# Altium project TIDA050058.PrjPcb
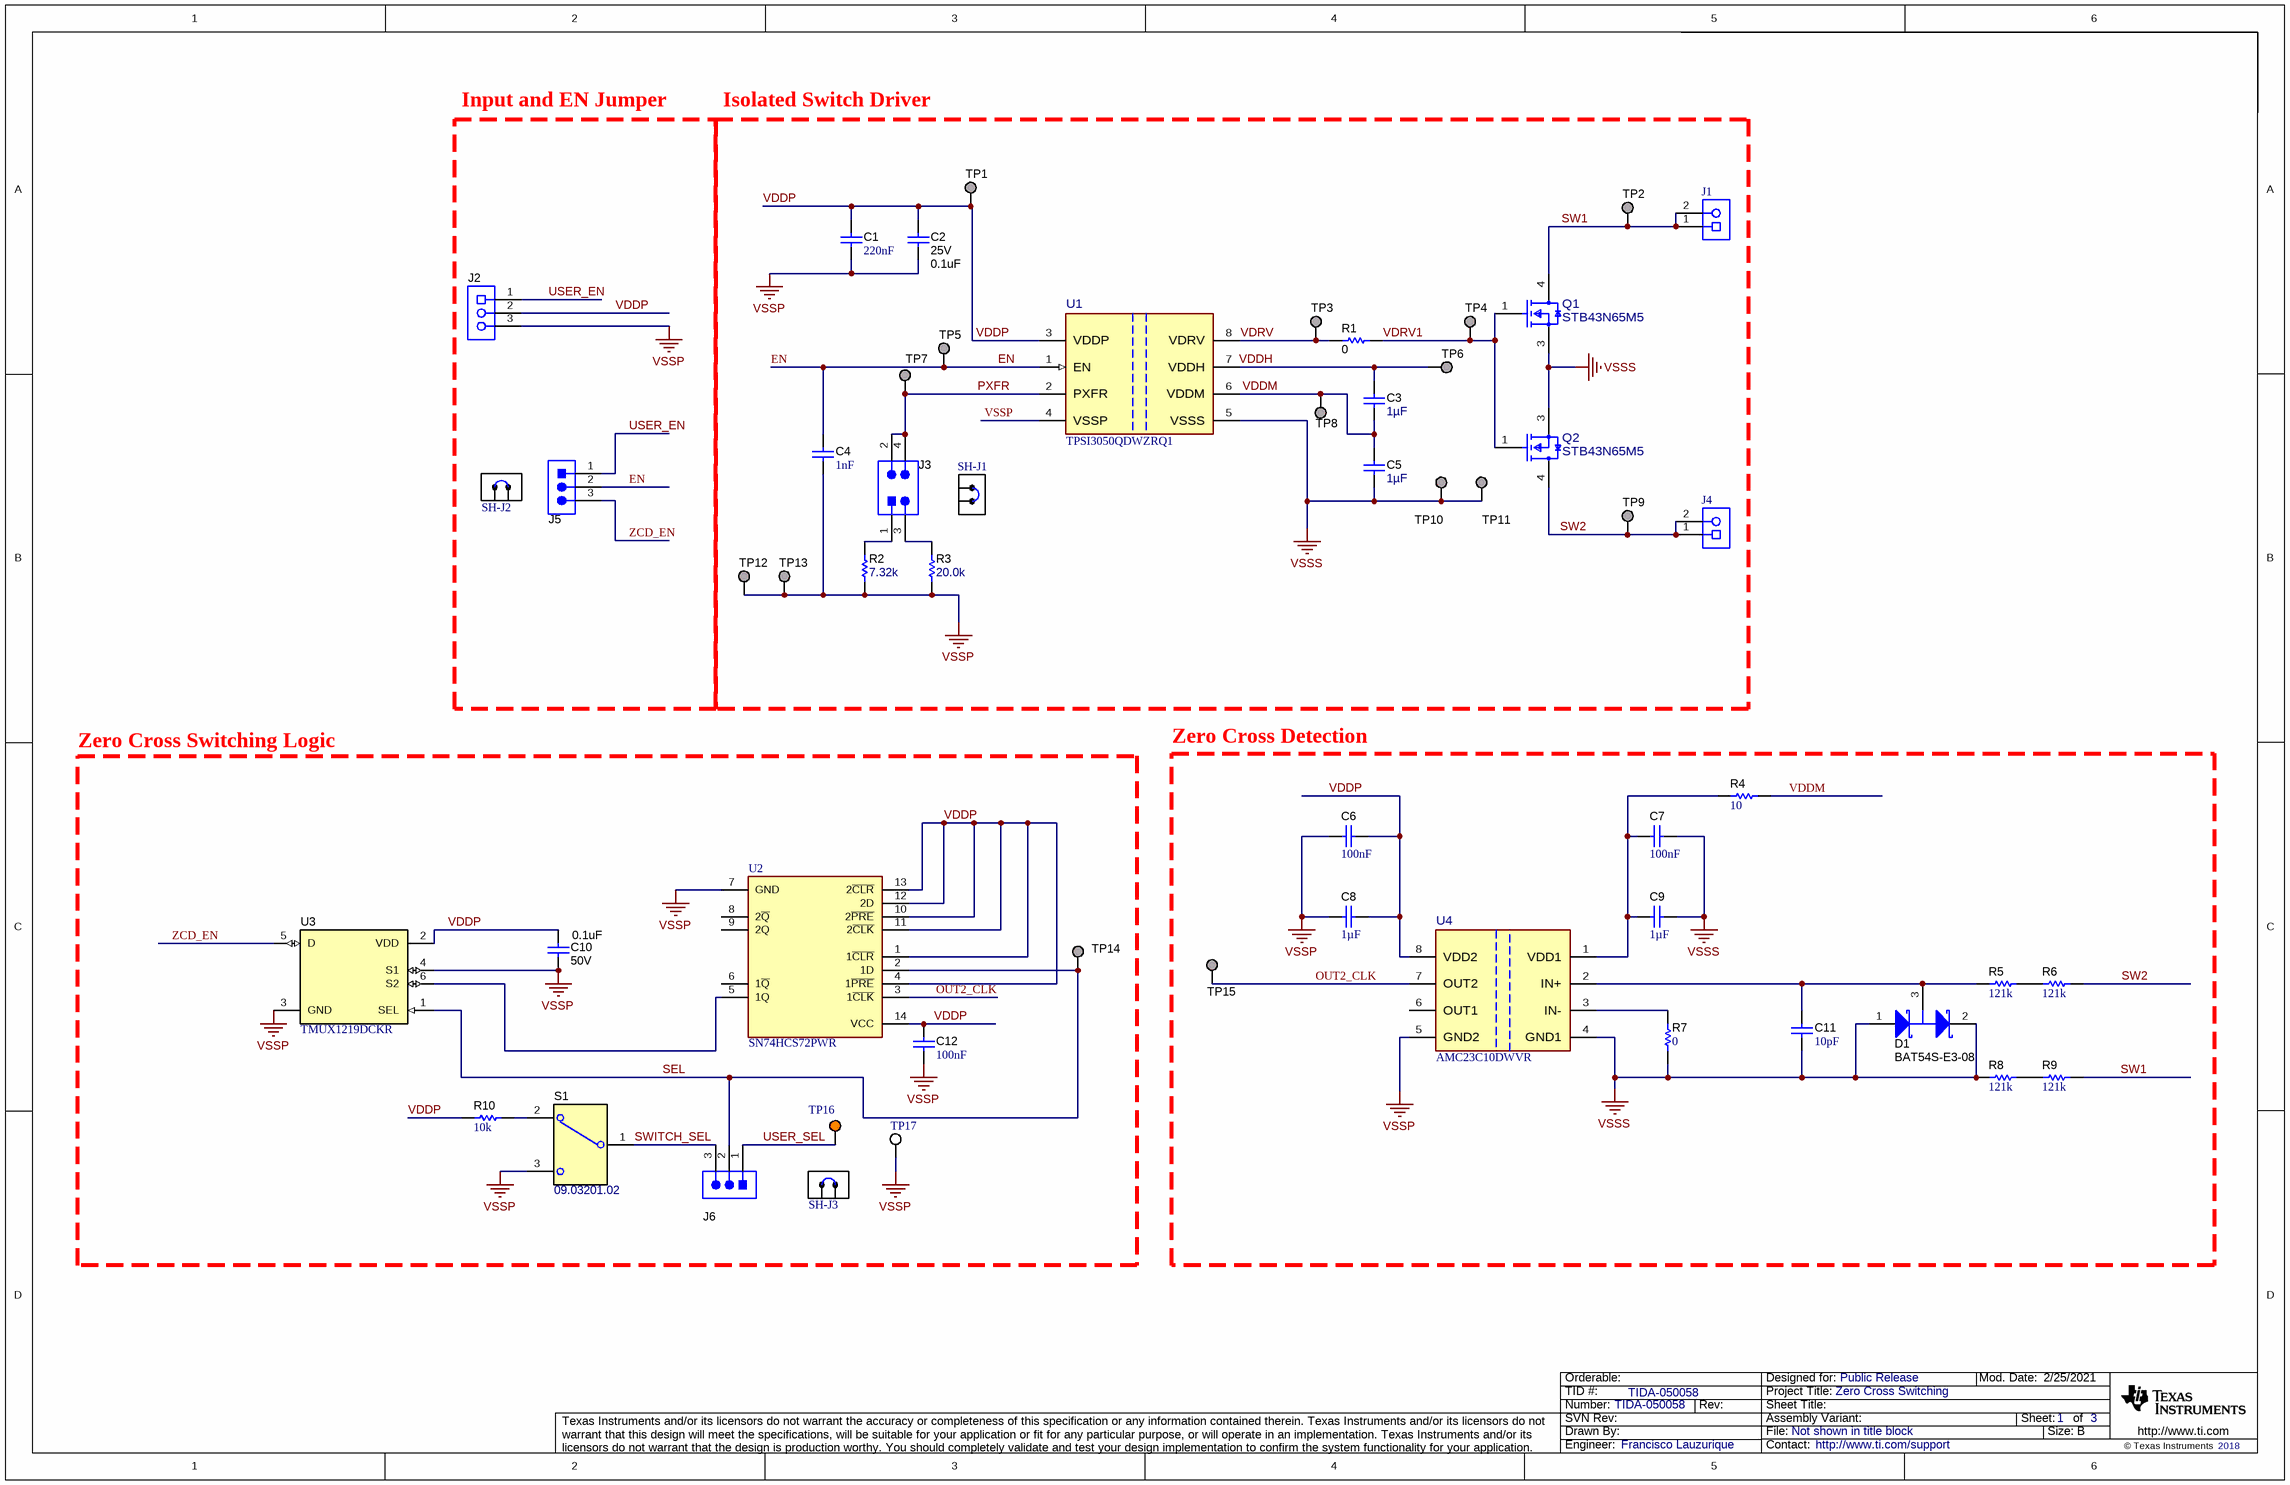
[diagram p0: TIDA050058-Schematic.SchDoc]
CopyrightYear: 2018; PCB_Layout: Francisco Lauzurique; PCB_Rev: E1; PRJ_Customer: Public Release; PRJ_Engineer: Francisco Lauzurique; PRJ_Number: TIDA-050058; PRJ_Title: Zero Cross Switching; TechSupport: http://www.ti.com/support; TID: TIDA-050058
2 sheets, 72 parts. Net scope: global (net labels, ports and power ports of the same name join across sheets).
Board file: TIDA050058-PCB.PcbDoc
Sheets:
  TIDA050058-Schematic.SchDoc
  TIDA050058-Hardware.SchDoc

## Sheet TIDA050058-Schematic.SchDoc
size 431 x 279 mm; Date: Not shown in title block; ApprovedBy: Not shown in title block; CheckedBy: Not shown in title block; Author: Not shown in title block; CompanyName: Not shown in title block; Engineer: Not shown in title block; Organization: Not shown in title block; Address1: Not shown in title block; Address2: Not shown in title block; Address3: Not shown in title block; Address4: Not shown in title block; DocumentNumber: 1; Revision: Use project parameter SCH_Rev; SheetNumber: 1; SheetTotal: 3; PageSetup: Record=PageOptions¦CenterHorizontal=True¦CenterVertical=True¦PrintScale=1.00¦XCorrection=1.00¦YCorrection=1.00¦PrintKind=0¦BorderSize=5000000¦LeftOffset=0¦BottomOffset=0¦Orientation=2¦PaperLength=1000¦PaperWidth=1000¦Scale=100¦PaperSource=15¦PrintQuality=600¦MediaType=1¦DitherType=10¦PaperKind=Letter¦PrintScaleMode=1

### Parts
C1  Cap_F: 220nF  [0603]  (hidden comment: GRM188R71E224KA88D)
C2  VDC_V: 25V  ValueDisplayed: 0.1uF  [0402]  (hidden comment: GRM155R71E104KE14D)
C3  Cap_F: 1µF  [0603]  (hidden comment: UMK107AB7105KA-T)
C4  Cap_F: 1nF  [0603]  (hidden comment: C0603C102J5RACAUTO)
C5  Cap_F: 1µF  [0603]  (hidden comment: UMK107AB7105KA-T)
C6  Cap_F: 100nF  [0603]  (hidden comment: GCM188R71E104KA57D)
C7  Cap_F: 100nF  [0603]  (hidden comment: GCM188R71E104KA57D)
C8  Cap_F: 1µF  [0603]  (hidden comment: GCM188R71E105KA64D)
C9  Cap_F: 1µF  [0603]  (hidden comment: GCM188R71E105KA64D)
C10  VDC_V: 50V  ValueDisplayed: 0.1uF  [0402]  (hidden comment: CGA2B3X7R1H103K050BB)
C11  Cap_F: 10pF  [0603]  (hidden comment: 0603ZC100KAT2A)
C12  Cap_F: 100nF  [0603]  (hidden comment: GCM188R71E104KA57D)
D1  BAT54S-E3-08  [SOT-23]
J1  0393570002  [MOLEX_39357-0002]  (value not drawn)
J2  0393570003  [MOLEX_39357-0003]  (value not drawn)
J3  PBC02DAAN  [Sullins_PxC02DAAN]  (value not drawn)
J4  0393570002  [MOLEX_39357-0002]  (value not drawn)
J5  PEC03SAAN  [CONN_PEC03SAAN]  (value not drawn)
J6  PEC03SAAN  [CONN_PEC03SAAN]  (value not drawn)
Q1  STB43N65M5  [FP-STB43N65M5_D2PAK-MFG]
Q2  STB43N65M5  [FP-STB43N65M5_D2PAK-MFG]
R1  ValueDisplayed: 0  [0603]  (hidden comment: ERJ-3GEY0R00V)
R2  ValueDisplayed: 7.32k  [0603]  (hidden comment: CRCW06037K32FKEA)
R3  ValueDisplayed: 20.0k  [0603]  (hidden comment: CRCW060320K0FKEA)
R4  ValueDisplayed: 10  [0603]  (hidden comment: CRCW060310R0JNEA)
R5  ValueDisplayed: 121k  [2010]  (hidden comment: CRCW2010121KFKEF)
R6  ValueDisplayed: 121k  [2010]  (hidden comment: CRCW2010121KFKEF)
R7  ValueDisplayed: 0  [0603]  (hidden comment: RC0603JR-070RL)
R8  ValueDisplayed: 121k  [2010]  (hidden comment: CRCW2010121KFKEF)
R9  ValueDisplayed: 121k  [2010]  (hidden comment: CRCW2010121KFKEF)
R10  ValueDisplayed: 10k  [0603]  (hidden comment: CRCW060310K0JNEA)
S1  09.03201.02  [SW_09_03201_02]
SH-J1  SNT-100-BK-G  [SNT-100-BK-G]  (value not drawn)
SH-J2  SNT-100-BK-G  [SNT-100-BK-G]  (value not drawn)
SH-J3  SNT-100-BK-G  [SNT-100-BK-G]  (value not drawn)
TP1  5019  [Keystone_5019]  (value not drawn)
TP2  5019  [Keystone_5019]  (value not drawn)
TP3  5019  [Keystone_5019]  (value not drawn)
TP4  5019  [Keystone_5019]  (value not drawn)
TP5  5019  [Keystone_5019]  (value not drawn)
TP6  5019  [Keystone_5019]  (value not drawn)
TP7  5019  [Keystone_5019]  (value not drawn)
TP8  5019  [Keystone_5019]  (value not drawn)
TP9  5019  [Keystone_5019]  (value not drawn)
TP10  5019  [Keystone_5019]  (value not drawn)
TP11  5019  [Keystone_5019]  (value not drawn)
TP12  5019  [Keystone_5019]  (value not drawn)
TP13  5019  [Keystone_5019]  (value not drawn)
TP14  5019  [Keystone_5019]  (value not drawn)
TP15  5019  [Keystone_5019]  (value not drawn)
TP16  5010  [Keystone5013]  (value not drawn)
TP17  5012  [Keystone5012]  (value not drawn)
U1  TPSI3050QDWZRQ1  [DWZ0008A-MFG]
U2  SN74HCS72PWR  [FP-PW0014A-IPC_C]
U3  TMUX1219DCKR  [DCK0006A_N]  (no BOM)
U4  AMC23C10DWVR  [DWV0008A-MFG]

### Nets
VSSP: C1.2 C2.2 C4.2 C6.2 C8.2 C10.2 C12.2 J2.3 R2.1 R3.1 S1.3 TP12.1 TP13.1 TP17.1 U1.4(VSSP) U2.7(GND) U3.3(GND) U3.4(S1) U4.5(GND2)
VSSS: C5.2 C7.1 C9.1 C11.2 D1.1(A) D1.2(K) Q1.3(S) Q2.3(S) R7.1 R8.1 TP10.1 TP11.1 U1.5(VSSS) U4.4(GND1)
EN: C4.1 J5.2 TP5.1 U1.1(EN)
OUT2_CLK: TP15.1 U2.3(1~{CLK}) U4.7(OUT2)
PXFR: J3.2 J3.4 TP7.1 U1.2(PXFR)
SEL: J6.2 TP14.1 U2.2(1D) U3.1(SEL)
SW1: J1.1 J1.2 Q1.4(D) R9.2 TP2.1
SW2: J4.1 J4.2 Q2.4(D) R6.2 TP9.1
SWITCH_SEL: J6.3 S1.1
USER_EN: J2.1 J5.1
USER_SEL: J6.1 TP16.1
VDDM: C3.2 C5.1 R4.2 TP8.1 U1.6(VDDM)
VDDP: C1.1 C2.1 C6.1 C8.1 C10.1 C12.1 J2.2 R10.1 TP1.1 U1.3(VDDP) U2.1(1~{CLR}) U2.4(1~{PRE}) U2.10(2~{PRE}) U2.11(2~{CLK}) U2.12(2D) U2.13(2~{CLR}) U2.14(VCC) U3.2(VDD) U4.8(VDD2)
VDRV: R1.1 TP3.1 U1.8(VDRV)
VDRV1: Q1.1(G) Q2.1(G) R1.2 TP4.1
ZCD_EN: J5.3 U3.5(D)
NetC3_1: C3.1 TP6.1 U1.7(VDDH)
NetC7_2: C7.2 C9.2 R4.1 U4.1(VDD1)
NetC11_1: C11.1 D1.3(C) R5.1 U4.2(IN+)
NetJ3_1: J3.1 R2.2
NetJ3_3: J3.3 R3.2
NetR5_2: R5.2 R6.1
NetR7_2: R7.2 U4.3(IN-)
NetR8_2: R8.2 R9.1
NetR10_2: R10.2 S1.2
NetU2_5: U2.5(1Q) U3.6(S2)

Not connected (* = marked no-connect by the designer): U2 6(1~{Q}) 8(2~{Q}) 9(2Q); U4 6(OUT1)

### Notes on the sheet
- Input and EN Jumper
- Isolated Switch Driver
- Zero Cross Switching Logic
- Zero Cross Detection
- Labels drawn without touching a wire or pin: VDDH

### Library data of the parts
C1 = CMP-0007415-4: CAP, CERM, 0.22 uF, 25 V, +/- 10%, X7R, 0603; Manufacturer: MuRata; TaMin_C: -55°C; Polarized: N; SizeAreaWB_mm2: 4.68; Value1: Unknown; U/M: EA; Value: 0.22uF; TaMax_C: 125°C; SizeZ_mm: 1; SizeX_mm: 1.6; SizeY_mm: 0.8; Value2: 25V; SizeArea_mm2: 1.28; AEC Category: Q200
C2 = CMP-0006659-2: CAP, CERM, 0.1 uF, 25 V, +/- 10%, X7R, 0402; Manufacturer: MuRata; TaMin_C: -55°C; Polarized: N; SizeAreaWB_mm2: 3; Value1: Unknown; U/M: EA; Value: 0.1uF; TaMax_C: 125°C; SizeZ_mm: 0.6; SizeX_mm: 1; SizeY_mm: 0.5; CompType: Capacitor; Cap_F: 100nF; AEC Category: Q200
C3 C5 = CMP-0007508-5: CAP, CERM, 1 uF, 50 V, +/- 10%, X7R, 0603; Manufacturer: Taiyo Yuden; TaMin_C: -55°C; Polarized: N; SizeAreaWB_mm2: 4.68; Value1: Unknown; U/M: EA; Value: 1uF; TaMax_C: 125°C; SizeZ_mm: 1; SizeX_mm: 1.6; SizeY_mm: 0.8; Value2: 50V; SizeArea_mm2: 1.28; AEC Category: Q200
C4 = CMP-0006844-4: CAP, CERM, 1000 pF, 50 V, +/- 5%, X7R, AEC-Q200 Grade 1, 0603; Manufacturer: Kemet; TaMin_C: -55°C; Polarized: N; SizeAreaWB_mm2: 4.68; Value1: Unknown; U/M: EA; Value: 1000pF; TaMax_C: 125°C; SizeZ_mm: 1; SizeX_mm: 1.6; SizeY_mm: 0.8; Value2: 50V; SizeArea_mm2: 1.28; AEC Qualified: Y; AEC Category: Q200
C6 C7 C12 = CMP-0084679-1: CAP, CERM, 0.1 µF, 25 V,+/- 10%, X7R, AEC-Q200 Grade 1, 0603; Manufacturer: MuRata; VDC_V: 25V; TaMin_C: -55°C; SizeY_mm: 0.8; Polarized: N; SizeArea_mm2: 1.28; SizeZ_mm: 1; SizeX_mm: 1.6; AEC Qualified: Y; AEC Category: Q200; Value: 0.1uF; ValueDisplayed: 0.1µF; TaMax_C: 125°C; U/M: EA; SizeAreaWB_mm2: 4.68
C8 C9 = CMP-0007139-4: CAP, CERM, 1 uF, 25 V, +/- 10%, X7R, AEC-Q200 Grade 1, 0603; Manufacturer: MuRata; TaMin_C: -55°C; Polarized: N; SizeAreaWB_mm2: 4.68; Value1: Unknown; U/M: EA; Value: 1uF; TaMax_C: 125°C; SizeZ_mm: 1; SizeX_mm: 1.6; SizeY_mm: 0.8; Value2: 25V; SizeArea_mm2: 1.28; AEC Qualified: Y; AEC Category: Q200
C10 = CMP-0006324-2: CAP, CERM, 0.01 uF, 50 V, +/- 10%, X7R, AEC-Q200 Grade 1, 0402; Manufacturer: TDK; TaMin_C: -55°C; ESR_ohm: 3.33065d; Polarized: N; SizeAreaWB_mm2: 3; Value1: 0.333065 ohm; U/M: EA; Value: 0.01uF; TaMax_C: 125°C; SizeZ_mm: 0.6; SizeX_mm: 1; SizeY_mm: 0.5; CompType: Capacitor; AEC Qualified: Y; Cap_F: 10nF; IRMS_A: 3.23373dA; AEC Category: Q200
C11 = CMP-0006811-4: CAP, CERM, 10 pF, 10 V, +/- 10%, X7R, 0603; Manufacturer: AVX; TaMin_C: -55°C; Polarized: N; SizeAreaWB_mm2: 4.68; Value1: Unknown; U/M: EA; Value: 10pF; TaMax_C: 125°C; SizeZ_mm: 1; SizeX_mm: 1.6; SizeY_mm: 0.8; Value2: 10V; SizeArea_mm2: 1.28; AEC Category: Q200
D1 = CMP-0028631-2: Diode, Schottky, 30 V, 0.2 A, SOT-23; Manufacturer: Vishay-Semiconductor; AEC Category: Q101; SizeX_mm: 2.5; Green_REACh: Incomplete; Value: 30V; SizeY_mm: 3; Value1: 0.2A; TJmax_C: 125°C; Value2: 0.7V; SizeArea_mm2: 7.5; SizeZ_mm: 1.1; Io_A: 200mA; Vf_V: 700mV; Green_Lifecycle: Not Set; SizeAreaWB_mm2: 14
J1 J4 = CMP-0055341-2: Terminal Block, 3.5 mm, 2x1, Tin, TH; Manufacturer: Molex; CNHeader: FALSE; CT: TRUE; Green_Lifecycle: Not Set; Green_REACh: Incomplete
J2 = CMP-0055340-2: Terminal Block, 3.5 mm, 3x1, Tin, TH; Manufacturer: Molex; CNHeader: FALSE; CT: TRUE; Green_REACh: Incomplete; Green_Lifecycle: Not Set
J3 = CMP-0054598-1: Header, 2.54mm, 2x2, Gold, TH; Manufacturer: Sullins Connector Solutions; CNHeader: TRUE; Current_A: 3A; Shrouded: N; Gender: Male; Voltage_V: 1.8kV; Row_Count: 2; RowSpacing_mm: 2.54; CT: FALSE; Cert_UL: Y
J5 J6 = CMP-0002338-1: Header, 100mil, 3x1, Tin, TH; Manufacturer: Sullins Connector Solutions; CNHeader: TRUE; Current_A: 3A; Green_Lifecycle: Not Set; Shrouded: N; Gender: Male; Green_REACh: Incomplete; Voltage_V: 1.8kV; Row_Count: 1; Pitch_mm: 2.54; CT: FALSE; Cert_UL: Y
Q1 Q2 = CMP-0088026-1: MOSFET N-CH 650V 42A; Manufacturer: STMicroelectronics; Rdson45_ohm: 0.058; SizeZ_mm: 4.83mm; AEC Qualified: Yes; ChMode: False; Vgs_V: 25V; QgTyp_nC: 100nC @ 10V
R1 = CMP-0025874-4: RES, 0, 5%, 0.1 W, AEC-Q200 Grade 0, 0603; Manufacturer: Panasonic; Power_W: 100mW; TempCo: 600 ppm/C; Value_Code: 0000; Value: 0; EIA_Code: E24; SizeX_mm: 1.6; SizeY_mm: 0.8; SizeZ_mm: 1; Value2: 0.1W; SizeArea_mm2: 1.28; AEC Qualified: Y; VDC_V: 50V; AEC Category: Q200; SizeAreaWB_mm2: 4.68
R2 = CMP-0022600-4: RES, 7.32 k, 1%, 0.1 W, AEC-Q200 Grade 0, 0603; Manufacturer: Vishay-Dale; Power_W: 100mW; TempCo: 100 ppm/C; Value_Code: 7k32; Value: 7.32k; EIA_Code: E96; SizeX_mm: 1.6; SizeY_mm: 0.8; SizeZ_mm: 1; Value2: 0.1W; SizeArea_mm2: 1.28; AEC Qualified: Y; VDC_V: 75V; AEC Category: Q200; AEC Grade: 0
R3 = CMP-0022204-4: RES, 20.0 k, 1%, 0.1 W, AEC-Q200 Grade 0, 0603; Manufacturer: Vishay-Dale; Power_W: 100mW; TempCo: 100 ppm/C; Value_Code: 20k0; Value: 20.0k; EIA_Code: E96; Res_ohm: 20k; SizeX_mm: 1.6; SizeY_mm: 0.8; SizeZ_mm: 1; Value2: 0.1W; SizeArea_mm2: 1.28; AEC Qualified: Y; VDC_V: 75V; AEC Category: Q200; AEC Grade: 0
R4 = CMP-0025703-4: RES, 10, 5%, 0.1 W, AEC-Q200 Grade 0, 0603; Manufacturer: Vishay-Dale; Power_W: 100mW; TempCo: 200 ppm/C; Value_Code: 10R0; Value: 10; EIA_Code: E24; SizeX_mm: 1.6; SizeY_mm: 0.8; SizeZ_mm: 1; Value2: 0.1W; SizeArea_mm2: 1.28; AEC Qualified: Y; VDC_V: 75V; AEC Category: Q200; AEC Grade: 0
R5 R6 R8 R9 = CMP-0016226-3: RES, 121 k, 1%, 0.75 W, AEC-Q200 Grade 0, 2010; Manufacturer: Vishay-Dale; Power_W: 750mW; TempCo: 100 ppm/C; Value: 121k; EIA_Code: E96; SizeX_mm: 5; SizeY_mm: 2.5; SizeZ_mm: 1.66; Value2: 0.75W; SizeArea_mm2: 12.5; AEC Qualified: Y; VDC_V: 400V; AEC Grade: 0; AEC Category: Q200
R7 = CMP-0025885-5: RES, 0, 5%, 0.1 W, 0603; Manufacturer: Yageo; Power_W: 100mW; TempCo: 200 ppm/C; Value_Code: 0000; Value: 0; EIA_Code: E24; SizeX_mm: 1.6; SizeZ_mm: 1; Value2: 0.1W; SizeArea_mm2: 1.28; AEC Qualified: N; VDC_V: 75V; AEC Category: Q200; SizeY_mm: 0.8; SizeAreaWB_mm2: 4.68
R10 = CMP-0025701-4: RES, 10 k, 5%, 0.1 W, AEC-Q200 Grade 0, 0603; Manufacturer: Vishay-Dale; Power_W: 100mW; TempCo: 200 ppm/C; Value_Code: 10k0; Value: 10k; EIA_Code: E24; SizeX_mm: 1.6; SizeY_mm: 0.8; SizeZ_mm: 1; Value2: 0.1W; SizeArea_mm2: 1.28; AEC Qualified: Y; VDC_V: 75V; AEC Category: Q200; AEC Grade: 0
S1 = CMP-0002207-1: Switch, SPDT, Slide, On-On, 2 Pos, TH; Manufacturer: EAO Switch; CurrentRating_mA: 500A; PositionCount: 2; VDC_V: 12V
SH-J1-SH-J3 = CMP-0003623-3: Shunt, 100mil, Gold plated, Black; Alternate PartNumber: 969102-0000-DA; Manufacturer: Samtec; Alternate Manufacturer: 3M; Value: 1x2
TP1-TP15 = CMP-0055162-1: Test Point, Miniature, SMT; Manufacturer: Keystone; CNHeader: FALSE; Green_Lifecycle: Active; Green_REACh: Passed; CT: TRUE
TP16 = CMP-0055150-1: Test Point, Multipurpose, Orange, TH; Manufacturer: Keystone; CNHeader: FALSE; Green_Lifecycle: Active; Green_REACh: Passed; ContactFinish: Silver; CT: TRUE
TP17 = CMP-0055149-1: Test Point, Multipurpose, White, TH; Manufacturer: Keystone; CNHeader: FALSE; Green_Lifecycle: Active; Green_REACh: Passed; ContactFinish: Silver; CT: TRUE
U1 = CMP-0095183-1: Automotive Reinforced Isolated Switch Driver With Integrated 10-V Gate Supply; Manufacturer: Texas Instruments; Min Supply Voltage: 3V; TJmax_C: +150°C; Output Voltage: 10V; AEC Qualified: Yes; Standoff Height: 0.36mm; Rise Time: 5ns; SizeZ_mm: 2.8mm; Number Of Drivers: 1; Max Supply Voltage: 5.5V; AEC Grade: Grade 1; TaMax_C: +125°C; Nominal Supply Current: 4-33mA; TaMin_C: -40°C
U2 = CMP-04902-000014-1: IC FF D-TYPE DUAL 2BIT 14TSSOP
U3 = CMP-0860319-1: 1-ch, 2:1 general-purpose analog multiplexer with 1.8-V logic control, DCK0006A (SOT-SC70-6); Alternate Manufacturer: Texas Instruments; SizeY_mm: 2; SizeArea_mm2: 4.2; SizeX_mm: 2.1; AEC Category: Q200; Rating: Catalog; CompType: IC; SizeZ_mm: 1.1; SizeAreaWB_mm2: 9.3; AEC Qualified: N
U4 = CMP-0092832-2: High-Speed Reinforced Differential Comparator w/ Reference, Open-Drain and Push-Pull Output; Manufacturer: Texas Instruments; Standoff Height: 0.36mm; AEC Qualified: No; CompType: IC; SizeZ_mm: 2.8mm; AEC Category: Q200; Number Of Channels: 1

## Sheet TIDA050058-Hardware.SchDoc
size 431 x 279 mm; Date: Not shown in title block; ApprovedBy: Not shown in title block; CheckedBy: Not shown in title block; Author: Not shown in title block; CompanyName: Not shown in title block; Engineer: Not shown in title block; Organization: Not shown in title block; Address1: Not shown in title block; Address2: Not shown in title block; Address3: Not shown in title block; Address4: Not shown in title block; DocumentNumber: 3; Revision: Use project parameter SCH_Rev; SheetNumber: 3; SheetTotal: 6; PageSetup: Record=PageOptions¦CenterHorizontal=True¦CenterVertical=True¦PrintScale=1.00¦XCorrection=1.00¦YCorrection=1.00¦PrintKind=0¦BorderSize=5000000¦LeftOffset=0¦BottomOffset=0¦Orientation=2¦PaperLength=1000¦PaperWidth=1000¦Scale=100¦PaperSource=15¦PrintQuality=600¦MediaType=1¦DitherType=10¦PaperKind=Letter¦PrintScaleMode=1
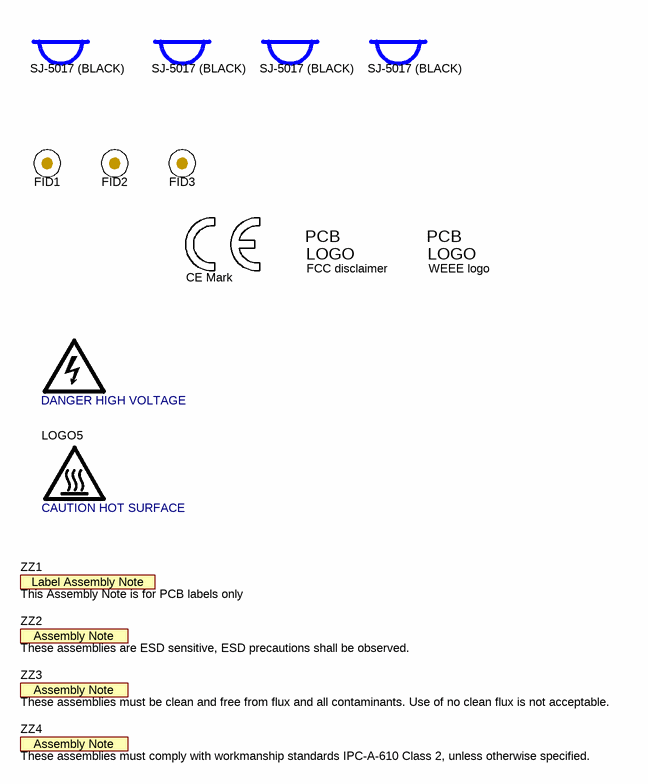
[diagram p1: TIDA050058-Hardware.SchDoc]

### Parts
FID1  Fiducial  [Fiducial10-20]  (value not drawn)
FID2  Fiducial  [Fiducial10-20]  (value not drawn)
FID3  Fiducial  [Fiducial10-20]  (value not drawn)
H1  SJ-5017 (BLACK)  [3M_SJ-5017BLACK]
H2  SJ-5017 (BLACK)  [3M_SJ-5017BLACK]
H3  SJ-5017 (BLACK)  [3M_SJ-5017BLACK]
H4  SJ-5017 (BLACK)  [3M_SJ-5017BLACK]
Logo1  CE Mark  [CE_Mark_5mm]  (no BOM)
Logo2  FCC disclaimer  [FCC_disclaimer]  (no BOM)
Logo3  WEEE logo  [WEEE_Minimum]  (no BOM)
LOGO4  DANGER HIGH VOLTAGE  [IEC_HighVoltage_Small]  (no BOM)
LOGO5  CAUTION HOT SURFACE  [IEC_HotSurface_Small]  (no BOM)
ZZ1  This Assembly Note is for PCB labels only  [AssemblyNoteLabel]  (no BOM)
ZZ2  These assemblies are ESD sensitive, ESD precautions shall be observed.  [AssemblyNote]  (no BOM)
ZZ3  These assemblies must be clean and free from flux and all contaminants. Use of no clean flux is not acceptable.  [AssemblyNote]  (no BOM)
ZZ4  These assemblies must comply with workmanship standards IPC-A-610 Class 2, unless otherwise specified.  [AssemblyNote]  (no BOM)

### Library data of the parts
FID1-FID3 = CMP-0077181-1: Fiducial mark.  There is nothing to buy or mount.
H1-H4 = CMP-0003997-1: Bumpon, Cylindrical, 0.75 X 0.38 inch, Black; Manufacturer: 3M
Logo1 = CMP-0074844-1: SymbolCreator: a0412235
Logo2 = CMP-0074847-1: FCC_disclaimer; Library Reference: Logo
Logo3 = CMP-0074769-1
LOGO4 = CMP-0074835-1: IEC 61010-1 High Voltage Warning; SymbolCreator: a0412235
LOGO5 = CMP-0074837-1: IEC 61010-1 Hot Surface Warning; SymbolCreator: a0412235
ZZ1 = CMP-0003616-3
ZZ2 = CMP-0077236-1
ZZ3 = CMP-0077237-1
ZZ4 = CMP-0077238-1

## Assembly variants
001: not fitted C11 FID1 FID2 FID3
